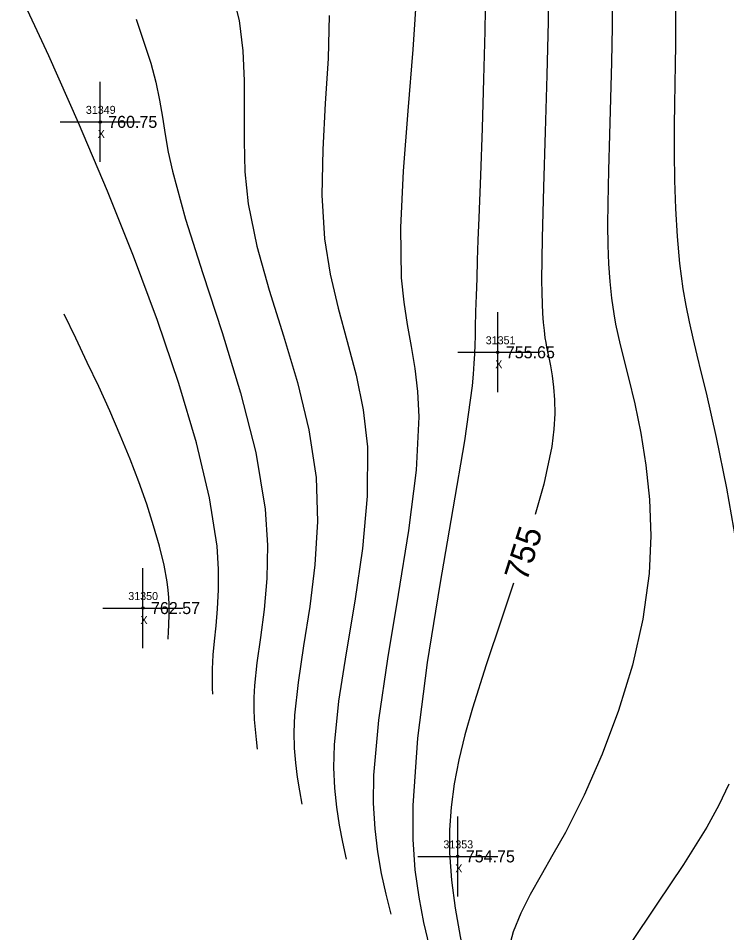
# Model space of a CAD drawing. Extents: x 1376587 to 1378239, y 1000335 to 1003031.
# Drawn here: x 1376611.3 to 1376699.8, y 1002752.4 to 1002866.7 of the extents above; entities that cross this region are included whole.
import ezdxf

# ---------------------------------------------------------------- set-up
doc = ezdxf.new("R2010")
doc.units = 0
for name, color, linetype in [('RD_DTM_Major1', 7, 'Continuous'), ('RD_DTM_Major1_Lbl', 7, 'Continuous'), ('RD_DTM_Minor1', 7, 'Continuous'), ('RD_EX_Misc', 7, 'Continuous'), ('RD_EX_Misc_txCode', 7, 'Continuous'), ('RD_EX_TX_Misc_ELEV', 7, 'Continuous'), ('RD_SMD_Locator', 7, 'Continuous')]:
    doc.layers.add(name, color=color, linetype=linetype)

msp = doc.modelspace()

# ---------------------------------------------------------------- linework, layer by layer
at = {"layer": 'RD_DTM_Major1'}
for points in [[(1376677.5, 1002872.16), (1376677.47, 1002866.26), (1376677.32, 1002859.55), (1376677.11, 1002852.5), (1376676.89, 1002845.56), (1376676.73, 1002839.22), (1376676.67, 1002833.94), (1376676.69, 1002832.39), (1376676.73, 1002831.01), (1376676.79, 1002829.78), (1376676.87, 1002828.68), (1376676.97, 1002827.68), (1376677.09, 1002826.76), (1376677.19, 1002826.17), (1376677.29, 1002825.59), (1376677.41, 1002825.02), (1376677.52, 1002824.45), (1376677.64, 1002823.87), (1376677.76, 1002823.27), (1376677.98, 1002821.99), (1376678.17, 1002820.58), (1376678.29, 1002819.01), (1376678.31, 1002817.27), (1376678.2, 1002815.34), (1376677.93, 1002813.19), (1376676.93, 1002808.48), (1376675.86, 1002804.67)], [(1376625.99, 1002866.56), (1376627.83, 1002861.06), (1376628.43, 1002858.68), (1376628.89, 1002856.46), (1376629.26, 1002854.32), (1376629.61, 1002852.17), (1376630, 1002849.95), (1376630.51, 1002847.58), (1376632.16, 1002841.58), (1376634.34, 1002834.77), (1376636.74, 1002827.43), (1376639.04, 1002819.88), (1376640.94, 1002812.42), (1376642.13, 1002805.36), (1376642.4, 1002800.85), (1376642.31, 1002796.68), (1376641.97, 1002792.83), (1376641.52, 1002789.33), (1376641.08, 1002786.15), (1376640.77, 1002783.32), (1376640.7, 1002781.82), (1376640.7, 1002780.42), (1376640.75, 1002779.09), (1376640.85, 1002777.82), (1376640.98, 1002776.59), (1376641.12, 1002775.38)], [(1376673.15, 1002796.09), (1376671.64, 1002791.62), (1376669.72, 1002785.89), (1376668.01, 1002780.51), (1376667.07, 1002777.16), (1376666.31, 1002774.02), (1376665.74, 1002771.03), (1376665.36, 1002768.14), (1376665.17, 1002765.29), (1376665.17, 1002762.42), (1376665.4, 1002759.01), (1376665.85, 1002755.52), (1376666.48, 1002751.96), (1376667.23, 1002748.35), (1376668.07, 1002744.7), (1376668.95, 1002741.03)]]:
    msp.add_lwpolyline(points, dxfattribs=at)
at = {"layer": 'RD_DTM_Minor1'}
for points in [[(1376637.7, 1002871.04), (1376638.85, 1002866.39), (1376639.34, 1002862.6), (1376639.5, 1002858.85), (1376639.49, 1002855.12), (1376639.47, 1002851.34), (1376639.58, 1002847.49), (1376639.98, 1002843.51), (1376641.07, 1002838.21), (1376642.63, 1002832.69), (1376644.41, 1002827), (1376646.14, 1002821.17), (1376647.58, 1002815.25), (1376648.47, 1002809.3), (1376648.65, 1002803.81), (1376648.33, 1002798.41), (1376647.69, 1002793.2), (1376646.92, 1002788.27), (1376646.23, 1002783.72), (1376645.78, 1002779.63), (1376645.7, 1002777.49), (1376645.75, 1002775.5), (1376645.9, 1002773.65), (1376646.12, 1002771.88), (1376646.39, 1002770.18), (1376646.69, 1002768.51)], [(1376635.55, 1002782.25), (1376635.53, 1002783.01), (1376635.51, 1002783.78), (1376635.51, 1002784.57), (1376635.52, 1002785.39), (1376635.55, 1002786.25), (1376635.61, 1002787.17), (1376635.77, 1002788.88), (1376635.97, 1002790.79), (1376636.16, 1002792.91), (1376636.28, 1002795.26), (1376636.28, 1002797.86), (1376636.1, 1002800.72), (1376635.17, 1002806.78), (1376633.54, 1002813.62), (1376631.33, 1002821.05), (1376628.66, 1002828.9), (1376625.64, 1002836.97), (1376622.39, 1002845.08), (1376618.77, 1002853.6), (1376615.06, 1002861.98), (1376611.25, 1002870.24)], [(1376661.08, 1002870.33), (1376660.59, 1002862.79), (1376659.95, 1002855.1), (1376659.35, 1002847.57), (1376659.01, 1002840.52), (1376659.12, 1002834.26), (1376659.44, 1002831.23), (1376659.88, 1002828.4), (1376660.36, 1002825.68), (1376660.82, 1002822.93), (1376661.16, 1002820.03), (1376661.32, 1002816.87), (1376660.98, 1002810.22), (1376660.03, 1002802.69), (1376658.75, 1002794.7), (1376657.41, 1002786.67), (1376656.29, 1002779), (1376655.66, 1002772.12), (1376655.62, 1002768.61), (1376655.8, 1002765.43), (1376656.15, 1002762.53), (1376656.63, 1002759.83), (1376657.2, 1002757.27), (1376657.82, 1002754.77)], [(1376669.66, 1002870.6), (1376669.57, 1002865.07), (1376669.41, 1002859.07), (1376669.22, 1002852.94), (1376669.01, 1002847.05), (1376668.82, 1002841.74), (1376668.71, 1002838.96), (1376668.63, 1002836.46), (1376668.55, 1002834.18), (1376668.48, 1002832.05), (1376668.42, 1002830.03), (1376668.38, 1002828.05), (1376668.35, 1002826.98), (1376668.32, 1002825.89), (1376668.28, 1002824.75), (1376668.21, 1002823.53), (1376668.11, 1002822.21), (1376667.97, 1002820.77), (1376667.01, 1002813.87), (1376665.57, 1002805.38), (1376663.94, 1002795.93), (1376662.38, 1002786.18), (1376661.16, 1002776.76), (1376660.55, 1002768.32), (1376660.57, 1002764.08), (1376660.83, 1002760.29), (1376661.3, 1002756.87), (1376661.91, 1002753.73), (1376662.62, 1002750.77)], [(1376685.45, 1002869.74), (1376685.47, 1002865.6), (1376685.4, 1002861.19), (1376685.28, 1002856.65), (1376685.14, 1002852.11), (1376685.01, 1002847.7), (1376684.93, 1002843.55), (1376684.92, 1002840.86), (1376684.96, 1002838.35), (1376685.04, 1002836), (1376685.19, 1002833.79), (1376685.4, 1002831.71), (1376685.68, 1002829.75), (1376685.92, 1002828.46), (1376686.18, 1002827.19), (1376686.48, 1002825.9), (1376686.81, 1002824.59), (1376687.16, 1002823.21), (1376687.53, 1002821.74), (1376688.31, 1002818.5), (1376689.06, 1002814.85), (1376689.71, 1002810.86), (1376690.17, 1002806.57), (1376690.33, 1002802.03), (1376690.13, 1002797.3), (1376689.34, 1002791.61), (1376688.02, 1002785.87), (1376686.29, 1002780.2), (1376684.24, 1002774.74), (1376682, 1002769.62), (1376679.65, 1002764.98), (1376678.09, 1002762.2), (1376676.6, 1002759.62), (1376675.23, 1002757.2), (1376674.05, 1002754.87), (1376673.12, 1002752.56), (1376672.5, 1002750.22)], [(1376693.39, 1002868.01), (1376693.41, 1002865.68), (1376693.39, 1002863.32), (1376693.35, 1002860.92), (1376693.3, 1002858.46), (1376693.26, 1002855.94), (1376693.23, 1002853.33), (1376693.23, 1002849.92), (1376693.28, 1002846.42), (1376693.41, 1002842.91), (1376693.61, 1002839.43), (1376693.92, 1002836.06), (1376694.34, 1002832.86), (1376694.69, 1002830.79), (1376695.1, 1002828.76), (1376695.56, 1002826.72), (1376696.07, 1002824.6), (1376696.63, 1002822.34), (1376697.22, 1002819.89), (1376698.49, 1002814.29), (1376699.78, 1002807.99), (1376700.95, 1002801.3)], [(1376650.11, 1002867.01), (1376649.97, 1002861.65), (1376649.63, 1002856.02), (1376649.31, 1002850.27), (1376649.21, 1002844.57), (1376649.52, 1002839.1), (1376650.24, 1002834.69), (1376651.24, 1002830.45), (1376652.38, 1002826.28), (1376653.47, 1002822.08), (1376654.36, 1002817.74), (1376654.89, 1002813.14), (1376654.87, 1002806.96), (1376654.26, 1002800.45), (1376653.3, 1002793.86), (1376652.23, 1002787.42), (1376651.29, 1002781.35), (1376650.74, 1002775.9), (1376650.67, 1002773.09), (1376650.77, 1002770.51), (1376651.02, 1002768.13), (1376651.37, 1002765.88), (1376651.79, 1002763.74), (1376652.25, 1002761.64)], [(1376629.99, 1002789.12), (1376630.04, 1002790.12), (1376630.08, 1002790.83), (1376630.09, 1002791.21), (1376630.11, 1002791.89), (1376630.12, 1002792.63), (1376630.11, 1002793.43), (1376630.07, 1002794.3), (1376629.99, 1002795.24), (1376629.86, 1002796.26), (1376629.47, 1002798.37), (1376628.9, 1002800.72), (1376628.17, 1002803.27), (1376627.31, 1002805.96), (1376626.32, 1002808.75), (1376625.24, 1002811.58), (1376623.99, 1002814.61), (1376622.68, 1002817.63), (1376621.3, 1002820.66), (1376619.88, 1002823.68), (1376618.43, 1002826.71), (1376616.97, 1002829.73)], [(1376700.05, 1002771.01), (1376698.81, 1002768.38), (1376697.3, 1002765.65), (1376694.39, 1002760.98), (1376691.08, 1002756.03), (1376687.69, 1002750.98)]]:
    msp.add_lwpolyline(points, dxfattribs=at)
at = {"layer": 'RD_EX_Misc'}
for p, q in [((1376621.49, 1002848.73), (1376621.49, 1002858.73)), ((1376616.49, 1002853.73), (1376626.49, 1002853.73)), ((1376671.19, 1002819.95), (1376671.19, 1002829.95)), ((1376666.19, 1002824.95), (1376676.19, 1002824.95)), ((1376626.84, 1002788), (1376626.84, 1002798)), ((1376621.84, 1002793), (1376631.84, 1002793)), ((1376666.19, 1002756.98), (1376666.19, 1002766.98)), ((1376661.19, 1002761.98), (1376671.19, 1002761.98))]:
    msp.add_line(p, q, dxfattribs=at)
at = {"layer": 'RD_SMD_Locator'}
for centre in [(1376621.49, 1002853.73), (1376671.19, 1002824.95), (1376626.84, 1002793), (1376666.19, 1002761.98)]:
    msp.add_circle(centre, 0.15, dxfattribs=at)

# ---------------------------------------------------------------- texts
at = {"layer": 'RD_DTM_Major1_Lbl'}
msp.add_text('755', height=3, rotation=72.4591, dxfattribs=at).set_placement((1376674.8, 1002796.2))
at = {"layer": 'RD_EX_Misc_txCode'}
for s, p in [('31349', (1376619.7, 1002854.73)), ('X', (1376621.18, 1002851.73)), ('31351', (1376669.68, 1002825.95)), ('X', (1376670.87, 1002822.95)), ('31350', (1376625, 1002794)), ('X', (1376626.52, 1002791)), ('31353', (1376664.39, 1002762.98)), ('X', (1376665.87, 1002759.98))]:
    msp.add_text(s, height=1, dxfattribs=at).set_placement(p)
at = {"layer": 'RD_EX_TX_Misc_ELEV'}
for s, p in [('760.75', (1376622.49, 1002852.98)), ('755.65', (1376672.19, 1002824.2)), ('762.57', (1376627.84, 1002792.25)), ('754.75', (1376667.19, 1002761.23))]:
    msp.add_text(s, height=1.5, dxfattribs=at).set_placement(p)

doc.saveas('drawing.dxf')
